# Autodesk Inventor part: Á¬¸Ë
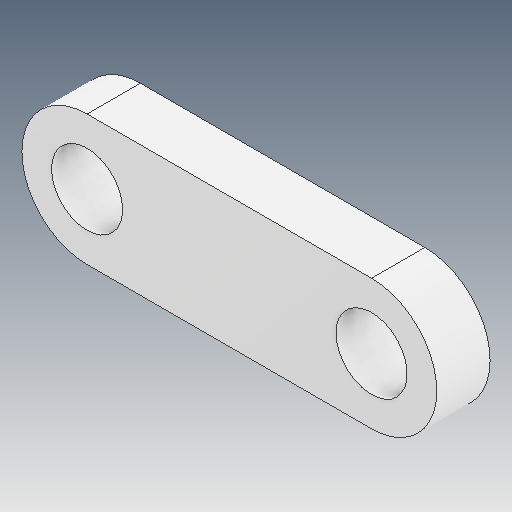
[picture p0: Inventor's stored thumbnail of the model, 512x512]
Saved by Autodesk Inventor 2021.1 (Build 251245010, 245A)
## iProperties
Created: 2021-06
Part Number: Á¬¸Ë
Material: Ogólny
Document SubType Name: Modeling
Designer: user
Density: 1 g/cm^3
Appearance: Domyślna
Author: user
Revision Number: ÈÎºÎ
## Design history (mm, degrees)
feature "Í¹Ì¨-À­Éì1"
node "Bryła1"
